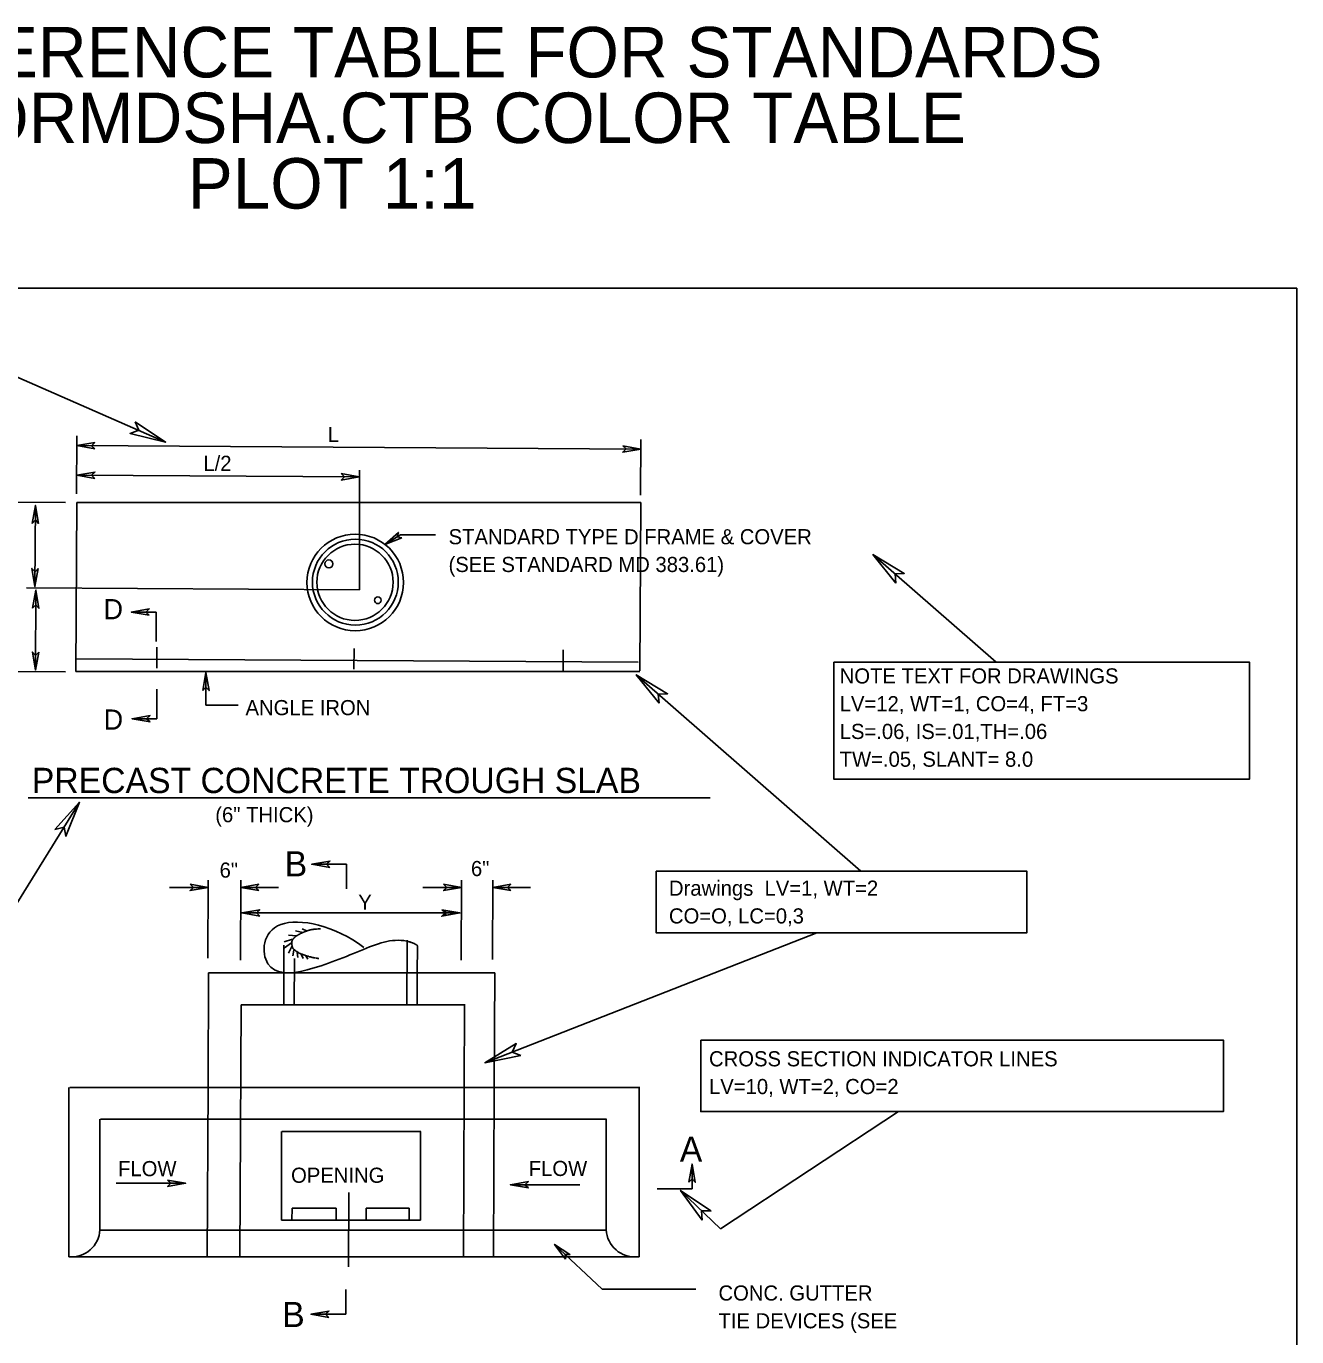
# Model space of a CAD drawing. Extents: x -0.5 to 19.9, y 5.2 to 17.3.
# Drawn here: x 2.73 to 7.77, y 12.13 to 17.33 of the extents above; entities that cross this region are included whole.
import ezdxf

# ---------------------------------------------------------------- set-up
doc = ezdxf.new("R2010")
doc.units = 0
for name, color, linetype in [('DETL-DIMS', 7, 'Continuous'), ('DETL-LINE', 7, 'Continuous'), ('DETL-NOTE', 7, 'Continuous'), ('DETL-TITL', 7, 'Continuous'), ('TTLB-TEXT', 7, 'Continuous')]:
    doc.layers.add(name, color=color, linetype=linetype)

msp = doc.modelspace()

# ---------------------------------------------------------------- linework, layer by layer
at = {"layer": 'DETL-DIMS'}
for p, q in [((2.5807, 15.9885), (3.284, 15.6805)), ((3.284, 15.6805), (3.1632, 15.7609)), ((3.1632, 15.7609), (3.1778, 15.7271)), ((2.9303, 15.4751), (2.9317, 15.7053)), ((3.1778, 15.7271), (3.143, 15.7147)), ((3.284, 15.6805), (3.143, 15.7147)), ((5.1671, 15.4696), (5.1684, 15.6913)), ((2.9318, 15.6664), (3.0034, 15.6786)), ((2.9318, 15.6664), (3.0032, 15.6534)), ((2.9318, 15.6664), (5.1682, 15.6528)), ((2.9898, 15.666), (3.0034, 15.6786)), ((3.0032, 15.6534), (2.9898, 15.666)), ((5.1102, 15.6532), (5.0966, 15.6406)), ((5.1682, 15.6528), (5.0966, 15.6406)), ((5.1682, 15.6528), (5.0968, 15.6658)), ((5.0968, 15.6658), (5.1102, 15.6532)), ((2.9324, 15.5491), (3.004, 15.5613)), ((2.9324, 15.5491), (4.0518, 15.5424)), ((2.9324, 15.5491), (3.0038, 15.5361)), ((2.9904, 15.5488), (3.004, 15.5613)), ((3.0038, 15.5361), (2.9904, 15.5488)), ((3.9938, 15.5427), (3.9802, 15.5302)), ((4.0518, 15.5424), (3.9802, 15.5302)), ((4.0518, 15.5424), (3.9804, 15.5554)), ((3.9804, 15.5554), (3.9938, 15.5427)), ((4.0522, 15.0949), (4.0522, 15.5697)), ((2.5551, 15.4426), (2.8876, 15.4406)), ((2.7681, 15.4298), (2.7551, 15.3584)), ((2.7661, 15.108), (2.7681, 15.4298)), ((2.7681, 15.4298), (2.7803, 15.3582)), ((2.7551, 15.3584), (2.7677, 15.3718)), ((2.7677, 15.3718), (2.7803, 15.3582)), ((4.1531, 15.2741), (4.2072, 15.3225)), ((4.2149, 15.3125), (4.1531, 15.2741)), ((4.1531, 15.2741), (4.2205, 15.3011)), ((4.2024, 15.3047), (4.2072, 15.3225)), ((4.2205, 15.3011), (4.2024, 15.3047)), ((4.3543, 15.3125), (4.2149, 15.3125)), ((6.0884, 15.2348), (6.1794, 15.1216)), ((6.0884, 15.2348), (6.2126, 15.1596)), ((6.5764, 14.8078), (6.0884, 15.2348)), ((2.7661, 15.108), (2.7539, 15.1796)), ((2.7665, 15.166), (2.7539, 15.1796)), ((2.7661, 15.108), (2.7791, 15.1794)), ((2.7791, 15.1794), (2.7665, 15.166)), ((6.1758, 15.1584), (6.2126, 15.1596)), ((6.1794, 15.1216), (6.1758, 15.1584)), ((2.7322, 15.103), (4.0522, 15.0949)), ((2.7699, 15.0937), (2.7568, 15.0223)), ((2.7679, 14.7766), (2.7699, 15.0937)), ((2.7699, 15.0937), (2.782, 15.0221)), ((2.7568, 15.0223), (2.7695, 15.0357)), ((2.7695, 15.0357), (2.782, 15.0221)), ((3.1479, 15.0069), (3.2194, 15.0195)), ((3.2059, 15.0069), (3.2194, 15.0195)), ((3.2467, 15.0069), (3.1479, 15.0069)), ((3.1479, 15.0069), (3.2194, 14.9943)), ((3.2194, 14.9943), (3.2059, 15.0069)), ((3.2467, 14.8895), (3.2467, 15.0069)), ((2.7679, 14.7766), (2.7558, 14.8482)), ((2.7683, 14.8346), (2.7558, 14.8482)), ((2.7679, 14.7766), (2.781, 14.848)), ((2.781, 14.848), (2.7683, 14.8346)), ((2.5591, 14.7721), (2.8879, 14.7701)), ((3.4439, 14.7673), (3.4313, 14.6958)), ((3.4439, 14.6375), (3.4439, 14.7673)), ((3.4439, 14.7673), (3.4565, 14.6958)), ((5.15, 14.7583), (5.241, 14.6451)), ((5.15, 14.7583), (5.2742, 14.6831)), ((6.0396, 13.9799), (5.15, 14.7583)), ((3.4313, 14.6958), (3.4439, 14.7093)), ((3.4439, 14.7093), (3.4565, 14.6958)), ((3.2498, 14.5836), (3.2498, 14.7011)), ((5.2374, 14.6819), (5.2742, 14.6831)), ((5.241, 14.6451), (5.2374, 14.6819)), ((3.5721, 14.6375), (3.4439, 14.6375)), ((3.151, 14.5836), (3.2225, 14.5962)), ((3.2498, 14.5836), (3.151, 14.5836)), ((3.151, 14.5836), (3.2225, 14.571)), ((3.209, 14.5836), (3.2225, 14.5962)), ((3.2225, 14.571), (3.209, 14.5836)), ((2.4408, 13.4428), (2.9424, 14.2526)), ((2.9424, 14.2526), (2.8456, 14.1444)), ((2.9424, 14.2526), (2.8886, 14.1178)), ((2.8456, 14.1444), (2.8814, 14.154)), ((2.8814, 14.154), (2.8886, 14.1178)), ((3.8637, 14.0073), (3.9352, 14.0199)), ((3.8637, 14.0073), (4.0018, 14.0073)), ((3.8637, 14.0073), (3.9352, 13.9947)), ((3.9217, 14.0073), (3.9352, 14.0199)), ((3.9352, 13.9947), (3.9217, 14.0073)), ((4.0018, 14.0073), (4.0018, 13.9411)), ((3.4526, 13.9152), (3.3811, 13.9278)), ((3.3811, 13.9278), (3.3946, 13.9152)), ((3.4513, 13.6342), (3.4527, 13.9446)), ((3.5807, 13.6263), (3.582, 13.9446)), ((3.5819, 13.9152), (3.6534, 13.9278)), ((3.6399, 13.9152), (3.6534, 13.9278)), ((4.0018, 13.9411), (4.0018, 13.9099)), ((4.4575, 13.9152), (4.386, 13.9278)), ((4.386, 13.9278), (4.3995, 13.9152)), ((4.4562, 13.6263), (4.4576, 13.9446)), ((4.5798, 13.6292), (4.5812, 13.9446)), ((4.5811, 13.9152), (4.6526, 13.9278)), ((4.6391, 13.9152), (4.6526, 13.9278)), ((3.2991, 13.9152), (3.4526, 13.9152)), ((3.4526, 13.9152), (3.3811, 13.9026)), ((3.3946, 13.9152), (3.3811, 13.9026)), ((3.5819, 13.9152), (3.732, 13.9152)), ((3.5819, 13.9152), (3.6534, 13.9026)), ((3.6534, 13.9026), (3.6399, 13.9152)), ((4.304, 13.9152), (4.4575, 13.9152)), ((4.4575, 13.9152), (4.386, 13.9026)), ((4.3995, 13.9152), (4.386, 13.9026)), ((4.5811, 13.9152), (4.6526, 13.9026)), ((4.5811, 13.9152), (4.7312, 13.9152)), ((4.6526, 13.9026), (4.6391, 13.9152)), ((3.5858, 13.8139), (3.6573, 13.8265)), ((3.6438, 13.8139), (3.6573, 13.8265)), ((4.4506, 13.8139), (4.3791, 13.8265)), ((4.3791, 13.8265), (4.3926, 13.8139)), ((4.3883, 13.8243), (4.4506, 13.8139)), ((4.3883, 13.8243), (4.3961, 13.8139)), ((3.5858, 13.8139), (4.4506, 13.8139)), ((3.5858, 13.8139), (3.6573, 13.8013)), ((3.6573, 13.8013), (3.6438, 13.8139)), ((4.4506, 13.8139), (4.3791, 13.8013)), ((4.3926, 13.8139), (4.3791, 13.8013)), ((4.3883, 13.8035), (4.4506, 13.8139)), ((4.3883, 13.8035), (4.3961, 13.8139)), ((5.8655, 13.7347), (4.5502, 13.2206)), ((4.5502, 13.2206), (4.6742, 13.2962)), ((4.5502, 13.2206), (4.6926, 13.2492)), ((4.6582, 13.2628), (4.6742, 13.2962)), ((4.6926, 13.2492), (4.6582, 13.2628)), ((5.4838, 12.5614), (6.1889, 13.0264)), ((5.3713, 12.8183), (5.3587, 12.7468)), ((5.3713, 12.7208), (5.3713, 12.8183)), ((5.3713, 12.8183), (5.3839, 12.7468)), ((3.0878, 12.7427), (3.3634, 12.7427)), ((3.3634, 12.7427), (3.2919, 12.7553)), ((3.2919, 12.7553), (3.3054, 12.7427)), ((3.3634, 12.7427), (3.2919, 12.7301)), ((3.3054, 12.7427), (3.2919, 12.7301)), ((4.6508, 12.7365), (4.7223, 12.7491)), ((4.6508, 12.7365), (4.9265, 12.7365)), ((4.6508, 12.7365), (4.7223, 12.7239)), ((4.7088, 12.7365), (4.7223, 12.7491)), ((4.7223, 12.7239), (4.7088, 12.7365)), ((5.3587, 12.7468), (5.3713, 12.7603)), ((5.3713, 12.7603), (5.3839, 12.7468)), ((5.2334, 12.7208), (5.3713, 12.7208)), ((5.3256, 12.7141), (5.4838, 12.5614)), ((5.3256, 12.7141), (5.411, 12.5967)), ((5.3256, 12.7141), (5.446, 12.6329)), ((5.411, 12.5967), (5.4091, 12.6335)), ((5.4091, 12.6335), (5.446, 12.6329)), ((5.0149, 12.3232), (4.8264, 12.4999)), ((4.8264, 12.4999), (4.8699, 12.4418)), ((4.8264, 12.4999), (4.8872, 12.4602)), ((4.8699, 12.4418), (4.8687, 12.4602)), ((4.8687, 12.4602), (4.8872, 12.4602)), ((3.9982, 12.2236), (3.9982, 12.3212)), ((5.0149, 12.3232), (5.386, 12.3232)), ((3.8602, 12.2236), (3.9317, 12.2362)), ((3.8602, 12.2236), (3.9982, 12.2236)), ((3.8602, 12.2236), (3.9317, 12.211)), ((3.9182, 12.2236), (3.9317, 12.2362)), ((3.9317, 12.211), (3.9182, 12.2236))]:
    msp.add_line(p, q, dxfattribs=at)
for points in [[(3.1632, 15.7609), (3.284, 15.6805), (3.143, 15.7147), (3.1778, 15.7271)], [(3.0032, 15.6534), (2.9318, 15.6664), (3.0034, 15.6786), (2.9898, 15.666)], [(5.0968, 15.6658), (5.1682, 15.6528), (5.0966, 15.6406), (5.1102, 15.6532)], [(3.0038, 15.5361), (2.9324, 15.5491), (3.004, 15.5613), (2.9904, 15.5488)], [(3.9804, 15.5554), (4.0518, 15.5424), (3.9802, 15.5302), (3.9938, 15.5427)], [(2.7551, 15.3584), (2.7681, 15.4298), (2.7803, 15.3582), (2.7677, 15.3718)], [(4.2205, 15.3011), (4.1531, 15.2741), (4.2072, 15.3225), (4.2024, 15.3047)], [(6.1794, 15.1216), (6.0884, 15.2348), (6.2126, 15.1596), (6.1758, 15.1584)], [(2.7791, 15.1794), (2.7661, 15.108), (2.7539, 15.1796), (2.7665, 15.166)], [(2.7568, 15.0223), (2.7699, 15.0937), (2.782, 15.0221), (2.7695, 15.0357)], [(3.2194, 14.9943), (3.1479, 15.0069), (3.2194, 15.0195), (3.2059, 15.0069)], [(2.781, 14.848), (2.7679, 14.7766), (2.7558, 14.8482), (2.7683, 14.8346)], [(3.4313, 14.6958), (3.4439, 14.7673), (3.4565, 14.6958), (3.4439, 14.7093)], [(5.241, 14.6451), (5.15, 14.7583), (5.2742, 14.6831), (5.2374, 14.6819)], [(3.2225, 14.571), (3.151, 14.5836), (3.2225, 14.5962), (3.209, 14.5836)], [(2.8456, 14.1444), (2.9424, 14.2526), (2.8886, 14.1178), (2.8814, 14.154)], [(3.9352, 13.9947), (3.8637, 14.0073), (3.9352, 14.0199), (3.9217, 14.0073)], [(3.3811, 13.9278), (3.4526, 13.9152), (3.3811, 13.9026), (3.3946, 13.9152)], [(3.6534, 13.9026), (3.5819, 13.9152), (3.6534, 13.9278), (3.6399, 13.9152)], [(4.386, 13.9278), (4.4575, 13.9152), (4.386, 13.9026), (4.3995, 13.9152)], [(4.6526, 13.9026), (4.5811, 13.9152), (4.6526, 13.9278), (4.6391, 13.9152)], [(3.6573, 13.8013), (3.5858, 13.8139), (3.6573, 13.8265), (3.6438, 13.8139)], [(4.3791, 13.8265), (4.4506, 13.8139), (4.3791, 13.8013), (4.3926, 13.8139)], [(5.4056, 13.3099), (7.4777, 13.3099), (7.4777, 13.0264), (5.4056, 13.0264)], [(4.6926, 13.2492), (4.5502, 13.2206), (4.6742, 13.2962), (4.6582, 13.2628)], [(5.3587, 12.7468), (5.3713, 12.8183), (5.3839, 12.7468), (5.3713, 12.7603)], [(3.2919, 12.7553), (3.3634, 12.7427), (3.2919, 12.7301), (3.3054, 12.7427)], [(4.7223, 12.7239), (4.6508, 12.7365), (4.7223, 12.7491), (4.7088, 12.7365)], [(5.411, 12.5967), (5.3256, 12.7141), (5.446, 12.6329), (5.4091, 12.6335)], [(4.8699, 12.4418), (4.8264, 12.4999), (4.8872, 12.4602), (4.8687, 12.4602)], [(3.9317, 12.211), (3.8602, 12.2236), (3.9317, 12.2362), (3.9182, 12.2236)]]:
    msp.add_lwpolyline(points, close=True, dxfattribs=at)
at = {"layer": 'DETL-LINE'}
for p, q in [((2.928, 14.7716), (2.932, 15.4408)), ((2.932, 15.4408), (5.1683, 15.4408)), ((5.1643, 14.7737), (5.1683, 15.4408)), ((3.2489, 14.7849), (3.2494, 14.867)), ((4.0308, 14.7801), (4.0313, 14.8622)), ((2.9297, 14.8212), (5.1569, 14.8077)), ((4.8602, 14.775), (4.8607, 14.8571)), ((2.928, 14.7716), (5.1643, 14.7716)), ((3.8032, 13.7234), (3.7711, 13.7258)), ((3.8275, 13.7363), (3.7995, 13.7426)), ((3.843, 13.7426), (3.8256, 13.7513)), ((3.7523, 13.5744), (3.7527, 13.6857)), ((3.7878, 13.7097), (3.7543, 13.6998)), ((3.7834, 13.6961), (3.7555, 13.6762)), ((3.7847, 13.6806), (3.7711, 13.6551)), ((3.7921, 13.6663), (3.7884, 13.644)), ((4.2409, 13.4477), (4.2419, 13.7062)), ((4.2818, 13.5734), (4.2823, 13.6841)), ((3.7942, 13.4497), (3.795, 13.6336)), ((3.8052, 13.6576), (3.8089, 13.6371)), ((3.8218, 13.6502), (3.8293, 13.6334)), ((3.8398, 13.6445), (3.8485, 13.6315)), ((3.4522, 13.1271), (3.454, 13.577)), ((3.454, 13.577), (4.5889, 13.577)), ((3.7523, 13.5744), (3.7523, 13.4517)), ((4.2818, 13.5734), (4.2812, 13.4497)), ((4.5869, 13.1236), (4.5889, 13.577)), ((3.5789, 12.4513), (3.5833, 13.4502)), ((3.5833, 13.4502), (4.4691, 13.4502)), ((4.4649, 12.4538), (4.4691, 13.4521)), ((2.9011, 12.4507), (2.9011, 13.1228)), ((2.904, 13.1228), (5.1643, 13.1228)), ((3.4522, 13.1271), (3.4492, 12.4507)), ((4.5869, 13.1236), (4.584, 12.4519)), ((5.1613, 12.4507), (5.1613, 13.1228)), ((3.0238, 12.5573), (3.0238, 12.9964)), ((3.0257, 12.9964), (5.0326, 12.9964)), ((5.0306, 12.5573), (5.0306, 12.9964)), ((3.7432, 12.5961), (3.7432, 12.9478)), ((3.7448, 12.9478), (4.2957, 12.9478)), ((4.2942, 12.5961), (4.2942, 12.9478)), ((4.0086, 12.4107), (4.0099, 12.7063)), ((3.7851, 12.5961), (3.7853, 12.6437)), ((3.7853, 12.6437), (3.9609, 12.6437)), ((3.9606, 12.5961), (3.9609, 12.6437)), ((4.0791, 12.5961), (4.0793, 12.6437)), ((4.0793, 12.6437), (4.2498, 12.6437)), ((4.2496, 12.5961), (4.2498, 12.6437)), ((3.7432, 12.5961), (4.2942, 12.5961)), ((3.0238, 12.5573), (5.0306, 12.5573)), ((2.9011, 12.4507), (5.1613, 12.4507))]:
    msp.add_line(p, q, dxfattribs=at)
msp.add_lwpolyline([(5.2291, 13.9799), (6.6982, 13.9799), (6.6982, 13.7347), (5.2291, 13.7347)], close=True, dxfattribs=at)
for centre, major_axis in [((4.0358, 15.1241), (0.1914, 0)), ((4.0364, 15.1254), (0.1702, 0)), ((4.0349, 15.1247), (0.1511, 0)), ((3.9314, 15.1978), (0.0159, 0)), ((4.1254, 15.0535), (0.0134, 0))]:
    msp.add_ellipse(centre, major_axis=major_axis, ratio=0.999935, dxfattribs=at)
for centre, major_axis, start_param, end_param in [((2.9101, 12.5643), (0.1139, 0), 4.632879, 6.222037), ((5.1444, 12.5643), (-0.1139, 0), 0.061149, 1.650306)]:
    msp.add_ellipse(centre, major_axis=major_axis, ratio=0.999935, start_param=start_param, end_param=end_param, dxfattribs=at)
msp.add_open_spline([(4.2531, 13.6997), (4.187, 13.716), (4.0846, 13.6776), (3.8323, 13.5707), (3.6584, 13.5698), (3.6713, 13.8264), (3.9573, 13.7643), (4.07, 13.6769)], degree=3, dxfattribs=at)
for points in [[(3.8981, 13.7513), (3.8944, 13.7513), (3.8827, 13.75), (3.8721, 13.7494), (3.8653, 13.7488), (3.8634, 13.7488), (3.8627, 13.7481), (3.8597, 13.7476), (3.8585, 13.7476), (3.8572, 13.7469), (3.856, 13.7469), (3.8553, 13.7463), (3.8548, 13.7463), (3.8535, 13.7457), (3.8529, 13.7457), (3.851, 13.7451), (3.8498, 13.7444), (3.8492, 13.7444), (3.8467, 13.7438), (3.8461, 13.7432), (3.8448, 13.7432), (3.8436, 13.7426), (3.843, 13.742), (3.8418, 13.742), (3.8393, 13.7407), (3.8374, 13.7401), (3.8367, 13.7394), (3.8343, 13.7388), (3.8336, 13.7388), (3.8319, 13.7383), (3.8305, 13.7376), (3.8299, 13.737), (3.8268, 13.7357), (3.8262, 13.7351), (3.825, 13.7351), (3.8237, 13.7346), (3.8231, 13.7339), (3.8225, 13.7339), (3.8188, 13.732), (3.8181, 13.7313), (3.8176, 13.7313), (3.8163, 13.7309), (3.8157, 13.7302), (3.8144, 13.7295), (3.8126, 13.7283), (3.8114, 13.7283), (3.8101, 13.7271), (3.8094, 13.7271), (3.8089, 13.7264), (3.8076, 13.7258), (3.807, 13.7252), (3.8057, 13.7252), (3.8039, 13.7234), (3.802, 13.7221), (3.8014, 13.7215), (3.8002, 13.7209), (3.7995, 13.7209), (3.7977, 13.719), (3.7964, 13.7184), (3.7958, 13.7178), (3.7946, 13.7159), (3.794, 13.7153), (3.7927, 13.7147), (3.7921, 13.7141), (3.7921, 13.7134), (3.7909, 13.7122), (3.7909, 13.7116), (3.789, 13.7097), (3.7878, 13.7072), (3.7878, 13.7066), (3.7865, 13.706), (3.7859, 13.7048), (3.7859, 13.7042), (3.7853, 13.7035), (3.7853, 13.7022), (3.7847, 13.701), (3.7841, 13.6991), (3.7841, 13.6979), (3.7847, 13.6892), (3.7847, 13.6862), (3.7853, 13.6855), (3.7853, 13.6837), (3.7859, 13.683), (3.7859, 13.6824), (3.7859, 13.6812), (3.7859, 13.6806), (3.7865, 13.6793), (3.7871, 13.6786), (3.7871, 13.6769), (3.7878, 13.6762), (3.7878, 13.6756), (3.7884, 13.6749), (3.789, 13.6738), (3.7915, 13.6712), (3.7921, 13.67), (3.7927, 13.6694), (3.7933, 13.6694)], [(3.7933, 13.6694), (3.7952, 13.6675), (3.7958, 13.6675), (3.7983, 13.665), (3.7995, 13.6644), (3.8008, 13.6632), (3.802, 13.6626), (3.8026, 13.6619), (3.8032, 13.6619), (3.8046, 13.6607), (3.8052, 13.6607), (3.8057, 13.6601), (3.807, 13.6595), (3.8076, 13.6589), (3.8089, 13.6582), (3.8089, 13.6576), (3.8094, 13.6576), (3.8101, 13.657), (3.8114, 13.6564), (3.8126, 13.6551), (3.8144, 13.6545), (3.8157, 13.6539), (3.8163, 13.6539), (3.8188, 13.6527), (3.82, 13.652), (3.8206, 13.652), (3.8218, 13.6514), (3.8225, 13.6508), (3.8231, 13.6508), (3.8244, 13.6502), (3.8262, 13.6502), (3.8262, 13.6496), (3.8268, 13.6496), (3.8281, 13.649), (3.8293, 13.649), (3.8299, 13.6483), (3.8305, 13.6483), (3.8319, 13.6477), (3.833, 13.6477), (3.8343, 13.6471), (3.8356, 13.6471), (3.8361, 13.6465), (3.8367, 13.6465), (3.8381, 13.6458), (3.8393, 13.6458), (3.8398, 13.6452), (3.8411, 13.6445), (3.843, 13.6445), (3.8436, 13.644), (3.8442, 13.644), (3.8448, 13.6434), (3.8467, 13.6434), (3.8479, 13.6428), (3.8485, 13.6428), (3.8492, 13.6421), (3.8504, 13.6421), (3.851, 13.6414), (3.8523, 13.6414), (3.8523, 13.6408), (3.8548, 13.6403), (3.8572, 13.6403), (3.8579, 13.6397), (3.8585, 13.6397), (3.8597, 13.6397), (3.8603, 13.6391), (3.8616, 13.6391), (3.8623, 13.6384), (3.8634, 13.6384), (3.8647, 13.6377), (3.8671, 13.6377), (3.8678, 13.6371), (3.869, 13.6371), (3.8697, 13.6371), (3.8708, 13.6366), (3.8721, 13.6366), (3.8739, 13.636), (3.8752, 13.636), (3.8777, 13.6353), (3.8808, 13.6353), (3.8814, 13.6347), (3.8832, 13.6347), (3.8852, 13.6347), (3.8864, 13.634), (3.8913, 13.634)], [(4.246, 13.7005), (4.2473, 13.7005), (4.2486, 13.6998), (4.2504, 13.6998), (4.2504, 13.6991), (4.2523, 13.6991), (4.2523, 13.6985), (4.2535, 13.6985), (4.2547, 13.6979), (4.256, 13.6979), (4.2566, 13.6973), (4.2584, 13.6973), (4.2591, 13.6967), (4.2604, 13.6967), (4.2609, 13.6961), (4.2616, 13.6961), (4.2622, 13.6954), (4.2641, 13.6954), (4.2646, 13.6948), (4.2653, 13.6948), (4.2659, 13.6942), (4.2665, 13.6942), (4.2678, 13.6936), (4.2684, 13.6936), (4.2684, 13.693), (4.2696, 13.693), (4.2696, 13.6923), (4.2709, 13.6923), (4.2715, 13.6917), (4.2721, 13.6917), (4.2733, 13.6904), (4.274, 13.6904), (4.274, 13.6899), (4.2747, 13.6899), (4.2752, 13.6899), (4.2752, 13.6892), (4.2764, 13.6892), (4.2764, 13.6886), (4.2771, 13.6886), (4.2771, 13.688), (4.2784, 13.688), (4.2784, 13.6874), (4.2789, 13.6874), (4.2802, 13.6862), (4.2808, 13.6862), (4.2814, 13.6862), (4.2814, 13.6855), (4.2821, 13.6855), (4.2827, 13.6849)]]:
    msp.add_spline(points, degree=3, dxfattribs=at)
at = {"layer": 'DETL-NOTE'}
msp.add_lwpolyline([(5.9329, 14.8078), (7.5815, 14.8078), (7.5815, 14.3446), (5.9329, 14.3446)], close=True, dxfattribs=at)
at = {"layer": 'DETL-TITL'}
msp.add_line((2.7389, 14.2707), (5.4429, 14.2707), dxfattribs=at)
at = {"layer": 'TTLB-TEXT'}
msp.add_lwpolyline([(0.3943, 16.2906), (7.7685, 16.2906), (7.7685, 5.9375), (0.3943, 5.9375)], close=True, dxfattribs=at)

# ---------------------------------------------------------------- texts
at = {"layer": 'DETL-DIMS'}
for s, p in [('CROSS SECTION INDICATOR LINES', (5.4384, 13.206)), ('LV=10, WT=2, CO=2 ', (5.4384, 13.096))]:
    msp.add_text(s, height=0.06, dxfattribs=at).set_placement(p)
at = {"layer": 'DETL-LINE'}
for s, height, p in [('SAMPLE PREFERENCE TABLE FOR STANDARDS', 0.2, (0.727, 17.126)), ('ATTACH CLORMDSHA.CTB COLOR TABLE', 0.2, (1.0473, 16.866)), ('PLOT 1:1', 0.2, (3.3719, 16.606)), ('Drawings  LV=1, WT=2', 0.06, (5.2795, 13.8823)), ('CO=O, LC=0,3', 0.06, (5.2795, 13.7723))]:
    msp.add_text(s, height=height, dxfattribs=at).set_placement(p)
at = {"layer": 'DETL-NOTE'}
for s, height, p in [('L', 0.06, (3.9267, 15.6803)), ('L/2', 0.06, (3.4338, 15.5664)), ('STANDARD TYPE D FRAME & COVER', 0.06, (4.4058, 15.2754)), ('(SEE STANDARD MD 383.61)', 0.06, (4.4058, 15.1654)), ('NOTE TEXT FOR DRAWINGS', 0.06, (5.9564, 14.7236)), ('ANGLE IRON', 0.06, (3.6009, 14.598)), ('LV=12, WT=1, CO=4, FT=3', 0.06, (5.9564, 14.6136)), ('LS=.06, IS=.01,TH=.06', 0.06, (5.9564, 14.5036)), ('TW=.05, SLANT= 8.0', 0.06, (5.9564, 14.3936)), ('(6" THICK)', 0.06, (3.481, 14.1736)), ('B', 0.1, (3.7561, 13.9588)), ('6"', 0.06, (3.4981, 13.954)), ('6"', 0.06, (4.4946, 13.9601)), ('Y', 0.06, (4.0479, 13.8265)), ('FLOW', 0.06, (3.0956, 12.7707)), ('FLOW', 0.06, (4.7237, 12.7714)), ('OPENING', 0.06, (3.7815, 12.7444)), ('CONC. GUTTER', 0.06, (5.4759, 12.2776)), ('TIE DEVICES (SEE', 0.06, (5.4759, 12.1676))]:
    msp.add_text(s, height=height, dxfattribs=at).set_placement(p)
at = {"layer": 'DETL-TITL'}
for s, height, p in [('D', 0.08, (3.038, 14.9783)), ('D', 0.08, (3.0384, 14.5406)), ('PRECAST CONCRETE TROUGH SLAB', 0.1, (2.7538, 14.2893)), ('A', 0.1, (5.3226, 12.8278)), ('B', 0.1, (3.7463, 12.1724))]:
    msp.add_text(s, height=height, dxfattribs=at).set_placement(p)

doc.saveas('drawing.dxf')
